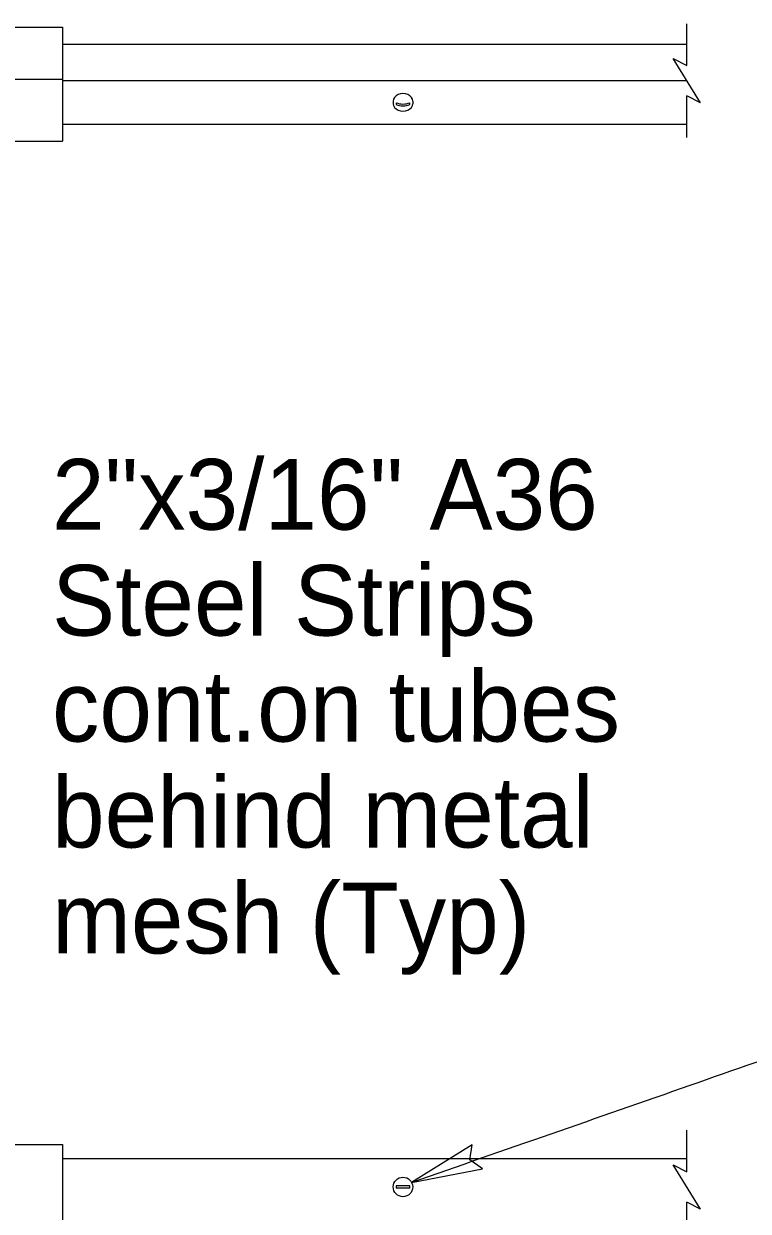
# Model space of a CAD drawing. Extents: x 0 to 2.83, y -0.03 to 1.83.
# Drawn here: x 0.8536 to 0.9865, y 1.4562 to 1.6742 of the extents above; entities that cross this region are included whole.
import ezdxf

# ---------------------------------------------------------------- set-up
doc = ezdxf.new("R2010")
doc.units = 0
for name, color, linetype in [('52', 7, 'Continuous'), ('54', 7, 'Continuous'), ('55', 7, 'Continuous'), ('57', 7, 'Continuous')]:
    doc.layers.add(name, color=color, linetype=linetype)

msp = doc.modelspace()

# ---------------------------------------------------------------- linework, layer by layer
at = {"layer": '52'}
for p, q in [((0.818989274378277, 1.6735807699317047), (0.8606559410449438, 1.6735807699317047)), ((0.8606559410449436, 1.6735807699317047), (0.8606559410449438, 1.6526423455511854)), ((0.8606559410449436, 1.6704492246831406), (0.9752392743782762, 1.670449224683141)), ((0.8189892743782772, 1.66402749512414), (0.8606559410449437, 1.66402749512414)), ((0.8606559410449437, 1.6637535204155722), (0.9752392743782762, 1.6637535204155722)), ((0.921365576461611, 1.660008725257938), (0.921365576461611, 1.6595186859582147)), ((0.9249463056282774, 1.6600087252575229), (0.9249463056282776, 1.659518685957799)), ((0.8606559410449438, 1.6557738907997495), (0.9752392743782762, 1.6557738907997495)), ((0.818989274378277, 1.6526423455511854), (0.8606559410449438, 1.6526423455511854)), ((0.8189892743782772, 1.4684728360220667), (0.8606559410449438, 1.4684728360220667)), ((0.8606559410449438, 1.4684728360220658), (0.8606559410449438, 1.4528478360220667)), ((0.8606559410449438, 1.4658686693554), (0.9752392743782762, 1.4658686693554)), ((0.9244029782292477, 1.4608909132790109), (0.9219089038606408, 1.4608909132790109)), ((0.9244029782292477, 1.4604297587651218), (0.9219089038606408, 1.4604297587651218))]:
    msp.add_line(p, q, dxfattribs=at)
msp.add_circle((0.9231559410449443, 1.4606603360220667), 0.0017903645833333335, dxfattribs=at)
for centre, radius, start, end in [((0.9231559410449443, 1.66286134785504), 0.003405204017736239, 248.51761783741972, 291.4823821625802), ((0.9231559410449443, 1.6625133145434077), 0.003405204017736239, 248.51761783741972, 291.4823821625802), ((0.9231559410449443, 1.4606603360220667), 0.0012681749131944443, 169.52431830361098, 190.47568169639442), ((0.9231559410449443, 1.4606603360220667), 0.0012681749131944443, 349.5243183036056, 10.475681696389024)]:
    msp.add_arc(centre, radius, start, end, dxfattribs=at)
for centre, major_axis, ratio, start_param, end_param in [((0.9231559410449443, 1.660008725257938), (-0.0017903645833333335, 2.1925642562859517e-19), 0.7546999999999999, 3.141592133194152, 6.283185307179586), ((0.9231559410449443, 1.6595186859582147), (-0.0017903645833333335, 2.1925642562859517e-19), 0.7546999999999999, 1.6226399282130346e-16, 3.141594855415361), ((0.9231559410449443, 1.6595186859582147), (-0.0012681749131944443, 1.5530663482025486e-19), 0.7547000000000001, 6.100350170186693, 6.466020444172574), ((0.9231559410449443, 1.6595186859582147), (-0.0012681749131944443, 1.5530663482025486e-19), 0.7547000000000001, 2.9587575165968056, 3.3244277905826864)]:
    msp.add_ellipse(centre, major_axis=major_axis, ratio=ratio, start_param=start_param, end_param=end_param, dxfattribs=at)
at = {"layer": '54'}
msp.add_lwpolyline([(0.924747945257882, 1.4614794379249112), (0.937718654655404, 1.463966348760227), (0.9354531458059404, 1.4656346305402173), (0.9358510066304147, 1.4683635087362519)], close=True, dxfattribs=at)
at = {"layer": '55'}
for p, q in [((0.9752392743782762, 1.6665491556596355), (0.9752392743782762, 1.6741924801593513)), ((0.9777539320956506, 1.659698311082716), (0.9727246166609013, 1.6678087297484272)), ((0.9727246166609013, 1.6678087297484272), (0.9752392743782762, 1.6665491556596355)), ((0.9777539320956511, 1.6596983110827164), (0.9752392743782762, 1.6609578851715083)), ((0.9752392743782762, 1.6533145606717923), (0.9752392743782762, 1.6609578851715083)), ((0.8606559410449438, 1.6557673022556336), (0.8606740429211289, 1.6557738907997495)), ((0.9752392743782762, 1.4634559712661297), (0.9752392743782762, 1.4710992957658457)), ((0.9777539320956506, 1.4566051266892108), (0.9727246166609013, 1.4647155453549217)), ((0.9727246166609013, 1.464715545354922), (0.9752392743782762, 1.4634559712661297)), ((0.9777539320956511, 1.4566051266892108), (0.9752392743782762, 1.4578647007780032)), ((0.9752392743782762, 1.4502213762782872), (0.9752392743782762, 1.4578647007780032))]:
    msp.add_line(p, q, dxfattribs=at)
msp.add_spline([(1.1233632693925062, 1.5109248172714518), (1.1159634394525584, 1.5109248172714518), (1.0732088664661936, 1.506813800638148), (1.0238766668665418, 1.4953029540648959), (0.9757777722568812, 1.4792699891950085), (0.924747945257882, 1.4614794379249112)], degree=3, dxfattribs=at)

# ---------------------------------------------------------------- texts
at = {"layer": '57'}
for s, p in [('2"x3/16" A36', (0.8587591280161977, 1.5813169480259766)), ('Steel Strips', (0.8587591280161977, 1.56186707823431)), ('cont.on tubes', (0.8587591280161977, 1.5424172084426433)), ('behind metal', (0.8587591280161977, 1.5229673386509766)), ('mesh (Typ)', (0.8587591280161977, 1.50351746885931))]:
    msp.add_text(s, height=0.012980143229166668, dxfattribs=at).set_placement(p)

doc.saveas('drawing.dxf')
